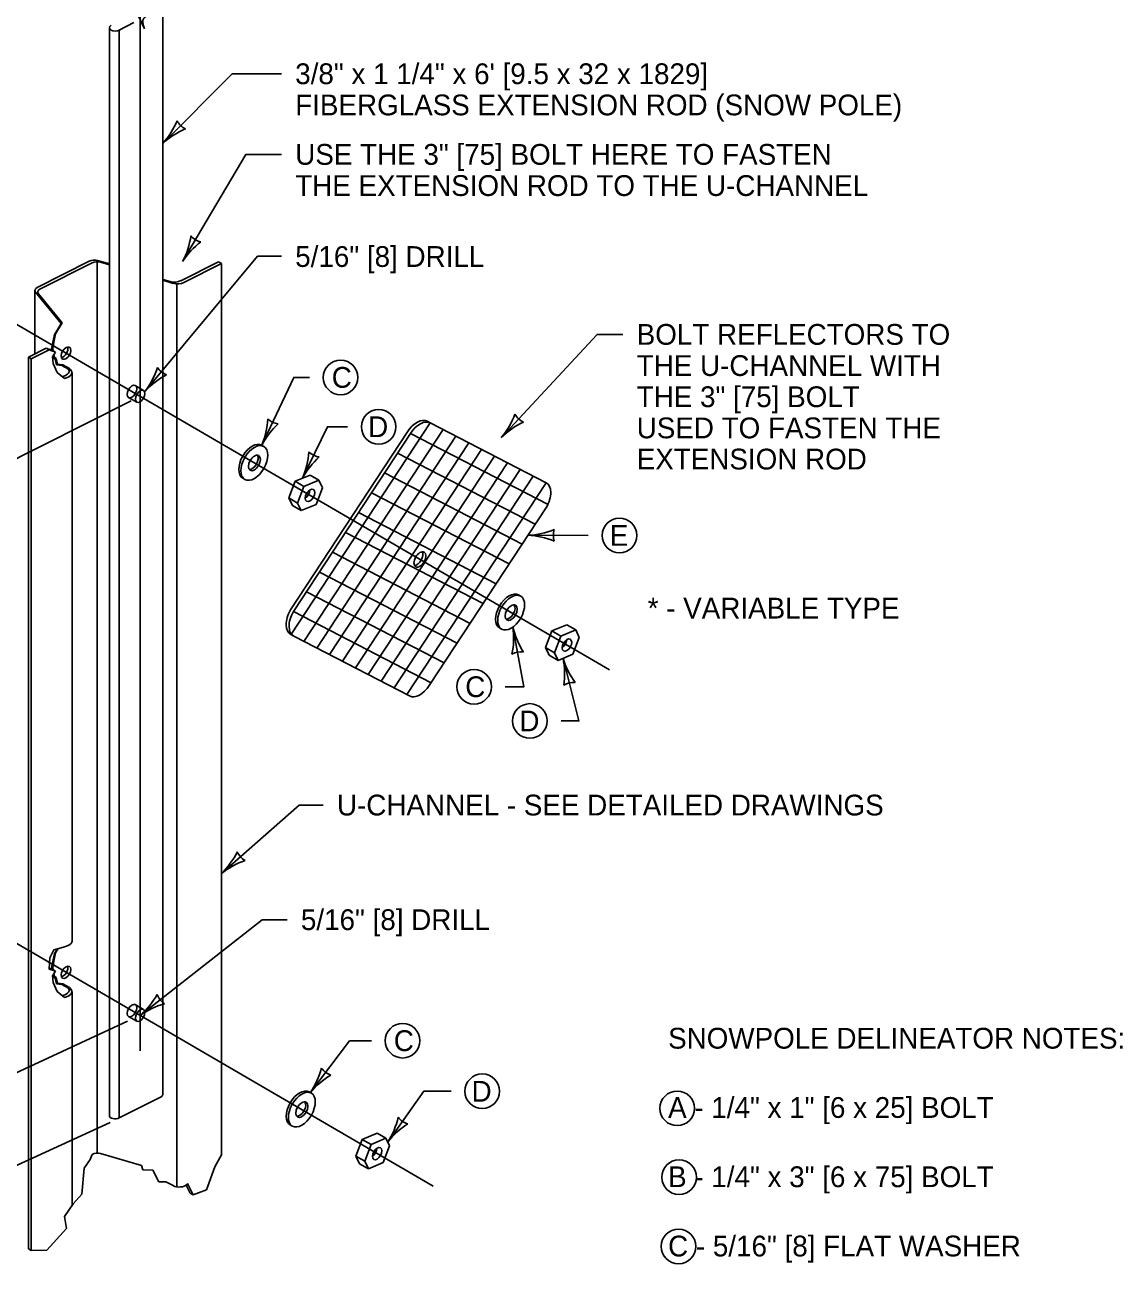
# Model space of a CAD drawing. Extents: x 49991.4 to 50021, y 49987.6 to 50011.4.
# Drawn here: x 50002.465 to 50005.633, y 49991.676 to 49995.327 of the extents above; entities that cross this region are included whole.
import ezdxf

# ---------------------------------------------------------------- set-up
doc = ezdxf.new("R2010")
doc.units = 0
for name, color, linetype in [('Level 1', 7, 'Continuous'), ('Level 2', 7, 'Continuous'), ('Level 25', 7, 'Continuous'), ('Level 3', 7, 'Continuous'), ('Level 4', 7, 'Continuous'), ('Level 5', 7, 'Continuous'), ('Level 6', 7, 'Continuous')]:
    doc.layers.add(name, color=color, linetype=linetype)

msp = doc.modelspace()

# ---------------------------------------------------------------- linework, layer by layer
at = {"layer": 'Level 1'}
for p, q in [((50002.8619, 49992.2395), (50002.8619, 49995.3805)), ((50002.7077, 49992.1788), (50002.7077, 49995.3199)), ((50002.7364, 49992.172), (50002.7364, 49995.3131)), ((50002.499, 49994.5698), (50002.6497, 49994.6456)), ((50002.5074, 49994.5649), (50002.6581, 49994.6407)), ((50002.673, 49994.6442), (50002.673, 49992.0702)), ((50002.7077, 49994.638), (50002.674, 49994.6478)), ((50002.7077, 49994.6355), (50002.6825, 49994.6429)), ((50002.914, 49994.5894), (50003.0228, 49994.6441)), ((50003.0312, 49994.6392), (50003.0228, 49994.6441)), ((50002.9224, 49994.5845), (50003.0312, 49994.6392)), ((50003.0312, 49994.6392), (50003.0312, 49994.1758)), ((50002.8832, 49994.5867), (50002.8619, 49994.5929)), ((50002.8916, 49994.5817), (50002.8619, 49994.5904)), ((50002.9025, 49994.58), (50002.9025, 49991.9728)), ((50002.4928, 49994.5612), (50002.4928, 49994.3778)), ((50002.5687, 49994.4658), (50002.4948, 49994.5561)), ((50002.5718, 49994.4674), (50002.5032, 49994.5512)), ((50002.5521, 49994.4359), (50002.5718, 49994.4674)), ((50002.5687, 49994.4658), (50002.5581, 49994.4479)), ((50002.5687, 49994.4658), (50002.5718, 49994.4674)), ((50002.549, 49994.4343), (50002.5456, 49994.4155)), ((50002.5487, 49994.4171), (50002.5521, 49994.4359)), ((50002.5581, 49994.4479), (50002.549, 49994.4343)), ((50002.549, 49994.4343), (50002.5521, 49994.4359)), ((50002.474, 49994.3683), (50002.5255, 49994.3942)), ((50002.4824, 49994.3634), (50002.5339, 49994.3893)), ((50002.5339, 49994.3893), (50002.5255, 49994.3942)), ((50002.5255, 49994.3942), (50002.5439, 49994.3877)), ((50002.5339, 49994.3893), (50002.5523, 49994.3827)), ((50002.5412, 49994.3929), (50002.5456, 49994.4155)), ((50002.5412, 49994.3929), (50002.5443, 49994.3945)), ((50002.5412, 49994.3929), (50002.5421, 49994.3883)), ((50002.5523, 49994.3827), (50002.5439, 49994.3877)), ((50002.5443, 49994.3945), (50002.5487, 49994.4171)), ((50002.5443, 49994.3945), (50002.5459, 49994.3865)), ((50002.5456, 49994.4155), (50002.5487, 49994.4171)), ((50002.4824, 49994.3634), (50002.474, 49994.3683)), ((50002.474, 49994.3683), (50002.474, 49991.7944)), ((50002.4824, 49994.3634), (50002.4824, 49991.7894)), ((50002.5523, 49994.3827), (50002.5432, 49994.3691)), ((50002.5432, 49994.3691), (50002.5459, 49994.3504)), ((50002.5452, 49994.3721), (50002.546, 49994.3674)), ((50002.5459, 49994.3504), (50002.5569, 49994.324)), ((50002.546, 49994.3674), (50002.5492, 49994.369)), ((50002.546, 49994.3674), (50002.5512, 49994.3632)), ((50002.5478, 49994.3761), (50002.5492, 49994.369)), ((50002.5492, 49994.369), (50002.5543, 49994.3648)), ((50002.5512, 49994.3632), (50002.5543, 49994.3648)), ((50002.5553, 49994.3463), (50002.5512, 49994.3632)), ((50002.5585, 49994.3479), (50002.5543, 49994.3648)), ((50002.5553, 49994.3463), (50002.5585, 49994.3479)), ((50002.5553, 49994.3463), (50002.5702, 49994.3449)), ((50002.5569, 49994.324), (50002.5778, 49994.307)), ((50002.5733, 49994.3465), (50002.5585, 49994.3479)), ((50002.5702, 49994.3449), (50002.5733, 49994.3465)), ((50002.5702, 49994.3449), (50002.5898, 49994.334)), ((50002.5721, 49994.3117), (50002.5828, 49994.317)), ((50002.5733, 49994.3465), (50002.5929, 49994.3356)), ((50002.5778, 49994.307), (50002.5913, 49994.3121)), ((50002.5898, 49994.334), (50002.5929, 49994.3356)), ((50002.5917, 49994.3293), (50002.5898, 49994.334)), ((50002.5917, 49994.3293), (50002.5961, 49994.3315)), ((50002.5929, 49994.3356), (50002.5961, 49994.3315)), ((50002.6001, 49994.3235), (50002.6001, 49992.6822)), ((50003.0312, 49994.1758), (50003.0312, 49992.0653)), ((50003.6337, 49994.1788), (50003.2321, 49993.5672)), ((50003.6337, 49994.1788), (50003.6254, 49994.1837)), ((50003.6337, 49994.1788), (50003.9685, 49994.0058)), ((50003.5686, 49994.1533), (50003.2307, 49993.6387)), ((50003.577, 49994.1484), (50003.239, 49993.6338)), ((50003.6709, 49994.1596), (50003.2693, 49993.548)), ((50003.7081, 49994.1404), (50003.3065, 49993.5288)), ((50003.9744, 49993.943), (50003.577, 49994.1484)), ((50003.1477, 49994.1143), (50003.1538, 49994.1108)), ((50003.7453, 49994.1212), (50003.3437, 49993.5096)), ((50003.7825, 49994.1019), (50003.3809, 49993.4904)), ((50003.8197, 49994.0827), (50003.4181, 49993.4711)), ((50003.8569, 49994.0635), (50003.4553, 49993.4519)), ((50003.9369, 49993.8859), (50003.5394, 49994.0912)), ((50003.2871, 49994.0282), (50003.2441, 49994.0102)), ((50003.2871, 49994.0282), (50003.3124, 49994.0134)), ((50003.8941, 49994.0443), (50003.4925, 49993.4327)), ((50003.8993, 49993.8287), (50003.5019, 49994.0341)), ((50003.9313, 49994.0251), (50003.5297, 49993.4135)), ((50003.0927, 49994.0191), (50003.0988, 49994.0155)), ((50003.2441, 49994.0102), (50003.2257, 49993.9621)), ((50003.2694, 49993.9955), (50003.2441, 49994.0102)), ((50003.2694, 49993.9955), (50003.2511, 49993.9473)), ((50003.3124, 49994.0134), (50003.2694, 49993.9955)), ((50003.3046, 49993.9434), (50003.3229, 49993.9916)), ((50003.3229, 49993.9916), (50003.3124, 49994.0134)), ((50003.9685, 49994.0058), (50003.5669, 49993.3943)), ((50003.2257, 49993.9621), (50003.2362, 49993.9402)), ((50003.2257, 49993.9621), (50003.2511, 49993.9473)), ((50003.2511, 49993.9473), (50003.2616, 49993.9254)), ((50003.8618, 49993.7715), (50003.4643, 49993.9769)), ((50003.2362, 49993.9402), (50003.2616, 49993.9254)), ((50003.2616, 49993.9254), (50003.3046, 49993.9434)), ((50003.8242, 49993.7143), (50003.4268, 49993.9197)), ((50003.9693, 49993.9352), (50003.6314, 49993.4207)), ((50003.7867, 49993.6572), (50003.3892, 49993.8625)), ((50003.7491, 49993.6), (50003.3517, 49993.8054)), ((50003.7116, 49993.5428), (50003.3141, 49993.7482)), ((50003.6741, 49993.4856), (50003.2766, 49993.691)), ((50003.8891, 49993.682), (50003.8952, 49993.6785)), ((50003.6365, 49993.4285), (50003.239, 49993.6338)), ((50003.8342, 49993.5868), (50003.8402, 49993.5833)), ((50004.0285, 49993.596), (50003.9855, 49993.578)), ((50004.0285, 49993.596), (50004.0539, 49993.5812)), ((50003.2399, 49993.5632), (50003.2315, 49993.5681)), ((50003.5746, 49993.3903), (50003.2399, 49993.5632)), ((50003.9855, 49993.578), (50003.9672, 49993.5298)), ((50004.0109, 49993.5632), (50003.9855, 49993.578)), ((50004.0109, 49993.5632), (50003.9926, 49993.5151)), ((50004.0539, 49993.5812), (50004.0109, 49993.5632)), ((50004.0461, 49993.5112), (50004.0644, 49993.5593)), ((50004.0644, 49993.5593), (50004.0539, 49993.5812)), ((50003.9672, 49993.5298), (50003.9777, 49993.508)), ((50003.9672, 49993.5298), (50003.9926, 49993.5151)), ((50003.9926, 49993.5151), (50004.0031, 49993.4932)), ((50004.0031, 49993.4932), (50004.0461, 49993.5112)), ((50003.9777, 49993.508), (50004.0031, 49993.4932)), ((50002.6001, 49992.5361), (50002.6001, 49991.9191)), ((50002.7364, 49992.172), (50002.857, 49992.2327)), ((50003.2848, 49992.247), (50003.2909, 49992.2435)), ((50003.2298, 49992.1518), (50003.2359, 49992.1482)), ((50003.4809, 49992.1279), (50003.4379, 49992.1099)), ((50003.4809, 49992.1279), (50003.5063, 49992.1131)), ((50003.4379, 49992.1099), (50003.4196, 49992.0618)), ((50003.4632, 49992.0951), (50003.4379, 49992.1099)), ((50003.4632, 49992.0951), (50003.4449, 49992.047)), ((50003.5063, 49992.1131), (50003.4632, 49992.0951)), ((50003.4984, 49992.0431), (50003.5167, 49992.0912)), ((50003.5167, 49992.0912), (50003.5063, 49992.1131)), ((50003.4196, 49992.0618), (50003.4301, 49992.0399)), ((50003.4196, 49992.0618), (50003.4449, 49992.047)), ((50003.4301, 49992.0399), (50003.4554, 49992.0251)), ((50003.4449, 49992.047), (50003.4554, 49992.0251)), ((50003.4554, 49992.0251), (50003.4984, 49992.0431))]:
    msp.add_line(p, q, dxfattribs=at)
for centre, major_axis, start_param, end_param in [((50002.6646, 49994.637), (0.021, 0), 1.101934, 2.356185), ((50002.673, 49994.6321), (0.021, 0), 1.101934, 2.356185), ((50002.5138, 49994.5612), (0.021, 0), 2.356185, 3.581499), ((50002.8953, 49994.6001), (0.0262, 0), 4.230578, 5.503569), ((50002.9038, 49994.5952), (0.0262, 0), 4.230578, 5.503569), ((50002.5222, 49994.5563), (0.021, 0), 2.356185, 3.581499), ((50002.5742, 49994.385), (0.0098, 0.0169), 3.5868, 5.833175), ((50002.5655, 49994.3284), (0.0262, 0), 5.435857, 6.341923), ((50002.5739, 49994.3235), (0.0262, 0), 5.435857, 6.843734), ((50003.5958, 49994.1306), (0.0304, 0.0526), 0.026952, 1.471473), ((50003.6042, 49994.1258), (0.0304, 0.0526), 0.026952, 1.471473), ((50003.1202, 49994.0667), (0.0275, 0.0476), 6.283184, 9.424776), ((50003.1202, 49994.0667), (0.0122, 0.0212), 3.391163, 6.028843), ((50003.287, 49993.9694), (0.0098, 0.0169), 3.153573, 9.424778), ((50003.2727, 49993.9774), (0.0098, 0.0169), 3.961375, 5.478491), ((50003.9389, 49993.9528), (0.0304, 0.0526), 4.71239, 6.310148), ((50003.6042, 49993.7845), (0.0122, 0.0212), 3.153573, 9.424778), ((50003.5958, 49993.7894), (0.0122, 0.0212), 3.487866, 5.932002), ((50003.8616, 49993.6344), (0.0275, 0.0476), 6.283184, 9.424776), ((50003.2611, 49993.6211), (0.0304, 0.0526), 1.570791, 3.168563), ((50003.2694, 49993.6163), (0.0304, 0.0526), 1.570791, 3.168563), ((50003.8616, 49993.6344), (0.0122, 0.0212), 3.391163, 6.028843), ((50004.0285, 49993.5372), (0.0098, 0.0169), 3.153573, 9.424778), ((50004.0142, 49993.5452), (0.0098, 0.0169), 3.961375, 5.478491), ((50003.6042, 49993.4433), (0.0304, 0.0526), 3.168548, 4.613061), ((50002.5742, 49992.5977), (0.0098, 0.0169), 3.5868, 5.833175), ((50002.8451, 49992.2395), (0.0168, 0), 5.49777, 6.283186), ((50003.2573, 49992.1994), (0.0275, 0.0476), 6.283184, 9.424776), ((50003.2573, 49992.1994), (0.0122, 0.0212), 3.391163, 6.028843), ((50002.7245, 49992.1789), (0.0168, 0), 3.146891, 5.49777), ((50003.4808, 49992.0691), (0.0098, 0.0169), 3.153573, 9.424778), ((50003.4665, 49992.0771), (0.0098, 0.0169), 3.961375, 5.478491)]:
    msp.add_ellipse(centre, major_axis=major_axis, ratio=0.57735, start_param=start_param, end_param=end_param, dxfattribs=at)
for centre, major_axis in [((50002.5826, 49994.3801), (0.0098, 0.0169)), ((50002.7967, 49994.2555), (0.0098, 0.0169)), ((50003.1263, 49994.0631), (0.0275, 0.0476)), ((50003.1263, 49994.0631), (0.0122, 0.0212)), ((50003.8677, 49993.6309), (0.0275, 0.0476)), ((50003.8677, 49993.6309), (0.0122, 0.0212)), ((50002.5826, 49992.5927), (0.0098, 0.0169)), ((50002.7967, 49992.4682), (0.0098, 0.0169)), ((50003.2634, 49992.1959), (0.0275, 0.0476)), ((50003.2634, 49992.1959), (0.0122, 0.0212))]:
    msp.add_ellipse(centre, major_axis=major_axis, ratio=0.57735, dxfattribs=at)
at = {"layer": 'Level 2'}
for centre in [(50003.3753, 49994.3101), (50003.4852, 49994.1676), (50004.1803, 49993.8538), (50003.7606, 49993.417), (50003.9217, 49993.3181), (50003.5543, 49992.395), (50003.7842, 49992.2489), (50004.3471, 49992.1997), (50004.3523, 49992.0009), (50004.3508, 49991.8011)]:
    msp.add_circle(centre, 0.05, dxfattribs=at)
at = {"layer": 'Level 25'}
for p, q in [((50002.8073, 49995.3233), (50002.8058, 49995.3242)), ((50003.1538, 49994.1108), (50003.1477, 49994.1143)), ((50003.0988, 49994.0155), (50003.0927, 49994.0191)), ((50003.8952, 49993.6785), (50003.8891, 49993.682)), ((50003.8402, 49993.5833), (50003.8342, 49993.5868)), ((50003.2909, 49992.2435), (50003.2848, 49992.247)), ((50003.2359, 49992.1482), (50003.2298, 49992.1518))]:
    msp.add_line(p, q, dxfattribs=at)
msp.add_ellipse((50003.2676, 49993.9807), major_axis=(0.0098, 0.0169), ratio=0.57735, start_param=4.589945, end_param=4.829787, dxfattribs=at)
at = {"layer": 'Level 3'}
for p, q in [((50001.9215, 49993.8157), (50002.7704, 49994.2423)), ((50003.9161, 49993.8542), (50004.0903, 49993.8539)), ((50001.921, 49992.062), (50002.7604, 49992.4511)), ((50001.0472, 49991.3949), (50002.7101, 49992.1589))]:
    msp.add_line(p, q, dxfattribs=at)
for points in [[(50003.2043, 49995.1868), (50003.0618, 49995.1868), (50002.8619, 49994.9854)], [(50003.2043, 49994.954), (50003.102, 49994.954), (50002.9189, 49994.6444)], [(50003.2043, 49994.6601), (50003.1357, 49994.6601), (50002.8109, 49994.2699)], [(50004.1901, 49994.4343), (50004.1156, 49994.4343), (50003.8393, 49994.1368)], [(50003.2853, 49994.3101), (50003.2402, 49994.3101), (50003.1476, 49994.1143)], [(50003.3952, 49994.1676), (50003.3374, 49994.1676), (50003.2656, 49994.0192)], [(50003.8725, 49993.5891), (50003.9047, 49993.417), (50003.8506, 49993.417)], [(50004.0174, 49993.4992), (50004.0631, 49993.3181), (50004.0117, 49993.3181)], [(50003.3248, 49993.0753), (50003.2557, 49993.0753), (50003.0312, 49992.8776)], [(50003.2207, 49992.7444), (50003.1492, 49992.7444), (50002.7965, 49992.468)], [(50003.4643, 49992.395), (50003.4011, 49992.395), (50003.2877, 49992.2449)], [(50003.6942, 49992.2489), (50003.6154, 49992.2489), (50003.5115, 49992.1022)]]:
    msp.add_lwpolyline(points, dxfattribs=at)
for centre, radius, start, end in [((50002.6886, 49995.1412), 0.233, 318.0324, 337.2822), ((50002.9522, 49995.0764), 0.0548, 207.3439, 243.0662), ((50003.0131, 49994.8224), 0.2223, 112.6611, 132.8446), ((50002.7128, 49994.753), 0.233, 332.2306, 351.4805), ((50002.9842, 49994.7548), 0.0548, 221.5422, 257.2645), ((50003.1055, 49994.5235), 0.2223, 126.8593, 147.0429), ((50002.6247, 49994.41), 0.233, 323.0433, 342.2932), ((50002.9757, 49994.1208), 0.2223, 117.672, 137.8555), ((50002.8929, 49994.3685), 0.0548, 212.3548, 248.0772), ((50003.6609, 49994.2867), 0.233, 319.9466, 339.1965), ((50003.9265, 49994.2307), 0.0548, 209.2581, 244.9805), ((50002.9323, 49994.2034), 0.233, 337.5147, 356.7645), ((50003.3445, 49994.0111), 0.2223, 132.1434, 152.3269), ((50003.2024, 49994.2302), 0.0548, 226.8262, 262.5485), ((50003.9958, 49993.9789), 0.2223, 114.5753, 134.7588), ((50003.0511, 49994.1103), 0.233, 336.9895, 356.2394), ((50003.3214, 49994.1346), 0.0548, 226.301, 262.0234), ((50003.4615, 49993.9142), 0.2223, 131.6182, 151.8017), ((50003.905, 49994.0869), 0.233, 272.73, 291.9798), ((50003.9065, 49993.6321), 0.2223, 67.3587, 87.5422), ((50004.0443, 49993.854), 0.0548, 162.0415, 197.7639), ((50003.6525, 49993.5573), 0.2223, 348.0393, 8.2229), ((50004.0992, 49993.6432), 0.233, 193.4106, 212.6605), ((50003.8961, 49993.4631), 0.0548, 82.7222, 118.4445), ((50003.7998, 49993.4537), 0.2223, 351.6175, 11.801), ((50004.2402, 49993.5673), 0.233, 196.9888, 216.2387), ((50004.0488, 49993.3749), 0.0548, 86.3003, 122.0227), ((50002.8688, 49993.0446), 0.233, 314.2116, 333.4615), ((50003.1274, 49992.9623), 0.0548, 203.5231, 239.2455), ((50003.1712, 49992.7048), 0.2223, 108.8403, 129.0238), ((50002.6439, 49992.6441), 0.233, 310.9092, 330.1591), ((50002.6439, 49992.6441), 0.233, 310.9092, 330.1591), ((50002.8974, 49992.5471), 0.0548, 200.2207, 235.9431), ((50002.8974, 49992.5471), 0.0548, 200.2207, 235.9431), ((50002.9263, 49992.2875), 0.2223, 105.5379, 125.7214), ((50002.9263, 49992.2875), 0.2223, 105.5379, 125.7214), ((50003.0951, 49992.376), 0.233, 325.7519, 345.0018), ((50003.365, 49992.3472), 0.0548, 215.0634, 250.7858), ((50003.4594, 49992.1037), 0.2223, 120.3806, 140.5641), ((50003.3149, 49992.2272), 0.233, 327.5338, 346.7836), ((50003.5856, 49992.2068), 0.0548, 216.8453, 252.5676), ((50003.6875, 49991.9663), 0.2223, 122.1625, 142.346)]:
    msp.add_arc(centre, radius, start, end, dxfattribs=at)
at = {"layer": 'Level 4'}
for p, q in [((50002.8064, 49994.2726), (50002.7827, 49994.2863)), ((50002.7866, 49994.2383), (50002.7629, 49994.252)), ((50002.8064, 49992.4852), (50002.7827, 49992.499)), ((50002.7866, 49992.4509), (50002.7629, 49992.4647))]:
    msp.add_line(p, q, dxfattribs=at)
for centre in [(50002.7728, 49994.2692), (50002.7728, 49992.4818)]:
    msp.add_ellipse(centre, major_axis=(0.0099, 0.0172), ratio=0.57735, dxfattribs=at)
at = {"layer": 'Level 5'}
for p, q in [((50002.7967, 49992.3661), (50002.7967, 49996.5957)), ((50004.1511, 49993.4657), (50002.2637, 49994.566)), ((50003.6421, 49991.9751), (50002.0146, 49992.9239))]:
    msp.add_line(p, q, dxfattribs=at)
at = {"layer": 'Level 6'}
for p, q in [((50002.7364, 49995.3131), (50002.7787, 49995.3344)), ((50002.784, 49995.3699), (50002.8093, 49995.3169)), ((50002.5778, 49992.6657), (50002.5913, 49992.6708)), ((50002.5339, 49992.6019), (50002.5359, 49992.6346)), ((50002.5359, 49992.6346), (50002.5477, 49992.6574)), ((50002.549, 49992.647), (50002.5456, 49992.6282)), ((50002.5477, 49992.6574), (50002.5685, 49992.6633)), ((50002.5487, 49992.6298), (50002.5521, 49992.6485)), ((50002.5579, 49992.6603), (50002.549, 49992.647)), ((50002.549, 49992.647), (50002.5521, 49992.6485)), ((50002.5521, 49992.6485), (50002.5598, 49992.6608)), ((50002.5685, 49992.6633), (50002.5778, 49992.6657)), ((50002.5339, 49992.6019), (50002.5523, 49992.5954)), ((50002.534, 49992.6038), (50002.5439, 49992.6003)), ((50002.5412, 49992.6056), (50002.5456, 49992.6282)), ((50002.5412, 49992.6056), (50002.5443, 49992.6072)), ((50002.5412, 49992.6056), (50002.5421, 49992.6009)), ((50002.5523, 49992.5954), (50002.5439, 49992.6003)), ((50002.5443, 49992.6072), (50002.5487, 49992.6298)), ((50002.5443, 49992.6072), (50002.5459, 49992.5992)), ((50002.5456, 49992.6282), (50002.5487, 49992.6298)), ((50002.5523, 49992.5954), (50002.5432, 49992.5818)), ((50002.5432, 49992.5818), (50002.5459, 49992.5631)), ((50002.5452, 49992.5847), (50002.546, 49992.5801)), ((50002.5459, 49992.5631), (50002.5569, 49992.5366)), ((50002.546, 49992.5801), (50002.5492, 49992.5817)), ((50002.546, 49992.5801), (50002.5512, 49992.5759)), ((50002.5478, 49992.5887), (50002.5492, 49992.5817)), ((50002.5492, 49992.5817), (50002.5543, 49992.5775)), ((50002.5512, 49992.5759), (50002.5543, 49992.5775)), ((50002.5553, 49992.559), (50002.5512, 49992.5759)), ((50002.5585, 49992.5606), (50002.5543, 49992.5775)), ((50002.5553, 49992.559), (50002.5585, 49992.5606)), ((50002.5733, 49992.5592), (50002.5585, 49992.5606)), ((50002.5702, 49992.5576), (50002.5733, 49992.5592)), ((50002.5733, 49992.5592), (50002.5929, 49992.5483)), ((50002.5553, 49992.559), (50002.5702, 49992.5576)), ((50002.5569, 49992.5366), (50002.5778, 49992.5197)), ((50002.5702, 49992.5576), (50002.5898, 49992.5467)), ((50002.5721, 49992.5243), (50002.5828, 49992.5297)), ((50002.5778, 49992.5197), (50002.5913, 49992.5248)), ((50002.5898, 49992.5467), (50002.5929, 49992.5483)), ((50002.5917, 49992.5419), (50002.5898, 49992.5467)), ((50002.5917, 49992.5419), (50002.5961, 49992.5442)), ((50002.5929, 49992.5483), (50002.5961, 49992.5442)), ((50002.6528, 49992.0524), (50002.6346, 49992.0274)), ((50002.6581, 49992.0667), (50002.6528, 49992.0524)), ((50002.8007, 49992.0344), (50002.6825, 49992.0689)), ((50003.0312, 49992.0653), (50003.012, 49992.0305)), ((50002.6346, 49992.0274), (50002.6284, 49991.9518)), ((50002.8007, 49992.0344), (50002.804, 49992.0219)), ((50002.804, 49992.0219), (50002.8328, 49992.0208)), ((50002.8328, 49992.0208), (50002.851, 49991.987)), ((50003.012, 49992.0305), (50002.9878, 49991.9643)), ((50002.851, 49991.987), (50002.8706, 49991.9873)), ((50002.8706, 49991.9873), (50002.8885, 49991.979)), ((50002.8969, 49991.9741), (50002.8885, 49991.979)), ((50002.9299, 49991.9783), (50002.9414, 49991.9545)), ((50002.9499, 49991.9496), (50002.9338, 49991.9825)), ((50002.6284, 49991.9518), (50002.6034, 49991.9238)), ((50002.9499, 49991.9496), (50002.9414, 49991.9545)), ((50002.9878, 49991.9643), (50002.9499, 49991.9496)), ((50002.6034, 49991.9238), (50002.5784, 49991.887)), ((50002.5784, 49991.887), (50002.5844, 49991.8532)), ((50002.5844, 49991.8532), (50002.5269, 49991.7905)), ((50002.4824, 49991.7894), (50002.474, 49991.7944)), ((50002.5269, 49991.7905), (50002.4824, 49991.7894))]:
    msp.add_line(p, q, dxfattribs=at)
for centre, major_axis, start_param, end_param in [((50002.7245, 49995.3199), (0.0168, 0), 2.356185, 5.49777), ((50002.5739, 49992.6822), (0.0262, 0), 5.435857, 6.284858), ((50002.5655, 49992.5411), (0.0262, 0), 5.435857, 6.341923), ((50002.5739, 49992.5361), (0.0262, 0), 5.435857, 6.843734), ((50002.673, 49992.0581), (0.021, 0), 1.101934, 2.356185), ((50002.9091, 49991.9875), (0.0262, 0), 4.230578, 5.948109)]:
    msp.add_ellipse(centre, major_axis=major_axis, ratio=0.57735, start_param=start_param, end_param=end_param, dxfattribs=at)
msp.add_open_spline([(50002.814, 49995.3521), (50002.8067, 49995.3488), (50002.8029, 49995.3339), (50002.8093, 49995.3169)], degree=2, dxfattribs=at)

# ---------------------------------------------------------------- texts
at = {"layer": 'Level 2'}
for s, p in [('3/8" x 1 1/4" x 6\' [9.5 x 32 x 1829]', (50003.2443, 49995.1568)), ('FIBERGLASS EXTENSION ROD (SNOW POLE)', (50003.2443, 49995.0668)), ('USE THE 3" [75] BOLT HERE TO FASTEN ', (50003.2443, 49994.924)), ('THE EXTENSION ROD TO THE U-CHANNEL', (50003.2443, 49994.834)), ('5/16" [8] DRILL', (50003.2443, 49994.6291)), ('BOLT REFLECTORS TO ', (50004.2301, 49994.4043)), ('THE U-CHANNEL WITH ', (50004.2301, 49994.3143)), ('C', (50003.3497, 49994.2801)), ('THE 3" [75] BOLT ', (50004.2301, 49994.2243)), ('D', (50003.4548, 49994.1376)), ('USED TO FASTEN THE ', (50004.2301, 49994.1343)), ('EXTENSION ROD', (50004.2301, 49994.0443)), ('E', (50004.1524, 49993.8238)), ('* - VARIABLE TYPE', (50004.2618, 49993.6139)), ('C', (50003.7351, 49993.387)), ('D', (50003.8914, 49993.2881)), ('U-CHANNEL - SEE DETAILED DRAWINGS', (50003.3648, 49993.0453)), ('5/16" [8] DRILL', (50003.2607, 49992.7144)), ('C', (50003.5288, 49992.365)), ('SNOWPOLE DELINEATOR NOTES:', (50004.3207, 49992.3721)), ('D', (50003.7534, 49992.2189)), ('A - 1/4" x 1" [6 x 25] BOLT', (50004.3207, 49992.1721)), ('B - 1/4" x 3" [6 x 75] BOLT', (50004.3207, 49991.9721)), ('C - 5/16" [8] FLAT WASHER', (50004.3207, 49991.7721))]:
    msp.add_text(s, height=0.06, dxfattribs=at).set_placement(p)
at = {"layer": 'Level 25'}
for s, p in [('DRAWN BY R.W. SCHULTZ', (50002.9046, 49991.973)), ('4/17/97', (50002.9046, 49991.9727))]:
    msp.add_text(s, height=0.000147, dxfattribs=at).set_placement(p)

doc.saveas('drawing.dxf')
